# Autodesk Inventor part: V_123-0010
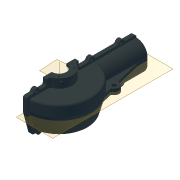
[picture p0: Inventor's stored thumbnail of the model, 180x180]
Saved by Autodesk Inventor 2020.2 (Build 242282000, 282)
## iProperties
Created: 2006-02
Part Number: V_123-0010
Document SubType Name: Modeling
Designer: F.Stasiak
Description: Obudowa - prawa
Material: L450
Project: Przekładnia X51
Mass: 3378.39 g
Surface Area: 1383.42 cm^2
Volume: 465.985 cm^3
Density: 7.25 g/cm^3
Appearance: Brąz armatni (nowy/polerowany)
Manager: www.cadconsulting.pl
Company: Fabian Stasiak CAD Consulting
Author: F.Stasiak
Subject: Zbiór ćwiczeń. Autodesk Inventor 2020. Kurs podstawowy
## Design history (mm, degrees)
sketch "Szkic1"
  geometry: L1 (0, -90)-(0, 90); A1 r 90 centre (0, 0) between (0, -90) and (0, 90); 2 further points
  constraints: 2 end point, 2 midpoint, 2 point on circle, 1 centre point, 1 coincident, 1 vertical, 1 other
  dimensions: "d0" = 90 radius of A1
extrude "Wyciągnięcie proste1" new body sketch "Szkic1" distance "d1" = 80; taper "d2" = 0 deg
node "Płaszczyzna konstrukcyjna4"
feature "Podział1"
feature "Szkic powierzchni2" dims angle "d38" = 15 deg
sketch "Szkic3"
  geometry: L1 (-78, 290)-(0, 290); L2 (0, 290)-(0, 150); L3 (0, 150)-(-78, 150); L4 (-78, 150)-(-78, 290); L5 (0, 0)-(0, 180) reference; L6 (34.5, 90)-(-126.5, 90) reference
  constraints: 10 end point, 2 horizontal, 2 parallel, 1 collinear, 1 perpendicular, 2 other
  dimensions: "d7" = 78 distance of L2.end L3.end; "d8" = 140 distance of L1.end L2.end; "d9" = 60 distance between parallel lines of L6 L3
extrude "Wyciągnięcie proste3" join sketch "Szkic3" distance "d10" = 40; taper "d11" = 0 deg
fillet "Zaokrąglenie1" dims "d12" = 30
node "Oś konstrukcyjna1"
feature "Skorupa1" dims "d13" = 5
sketch "Szkic4"
  geometry: L1 (2, 196.603)-(80, 196.603); L2 (80, 196.603)-(80, 156.603); L3 (80, 156.603)-(2, 156.603); L4 (2, 156.603)-(2, 196.603); L5 (80, -13.397)-(80, 276.603) reference; L6 (2, 153.741)-(2, 276.603) reference; L7 (2, 246.603)-(80, 246.603); L8 (80, 246.603)-(80, 276.603); L9 (80, 276.603)-(2, 276.603); L10 (2, 276.603)-(2, 246.603); L11 (2, 276.603)-(80, 276.603) reference
  constraints: 16 end point, 5 collinear, 4 parallel, 2 horizontal, 2 perpendicular
  dimensions: "d14" = 40 distance of L1.end L2.end; "d15" = 30 distance between parallel lines of L9 L7; "d16" = 50 distance between parallel lines of L1 L7
extrude "Wyciągnięcie proste4" join sketch "Szkic4" stored distance "d17" = 30; taper "d18" = 0 deg
node "Płaszczyzna konstrukcyjna1"
sketch "Szkic5"
  geometry: C1 r 27.5 at (0, -22.5) reference
extrude "Wyciągnięcie proste5" cut sketch "Szkic5" distance "d19" = 25; taper "d20" = 0 deg
node "Płaszczyzna konstrukcyjna2"
sketch "Szkic6"
  geometry: C1 r 23.5 at (0, -18) reference
extrude "Wyciągnięcie proste6" cut sketch "Szkic6" extent not by distance; stored distance "d21" = 12; taper "d22" = 0 deg
sketch "Szkic7"
  geometry: C1 r 18.1 at (0, 33.423) reference; C2 r 22.5 at (0, 33.423)
  constraints: 1 centre point, 1 coincident
  dimensions: "d23" = 45 diameter of C2
extrude "Wyciągnięcie proste7" cut sketch "Szkic7" stored distance "d24" = 12; taper "d25" = 0 deg
sketch "Szkic8"
  geometry: C1 r 23.5 at (0, 34.577) reference; C2 r 20 at (0, 34.577)
  constraints: 1 centre point, 1 coincident
  dimensions: "d26" = 40 diameter of C2
extrude "Wyciągnięcie proste8" cut sketch "Szkic8" extent not by distance; stored distance "d27" = 12; taper "d28" = 0 deg
sketch "Szkic9"
  geometry: L1 (80, 76.603)-(104, 76.603); L2 (104, 76.603)-(104, 40.603); L3 (104, 40.603)-(80, 40.603); L4 (80, 40.603)-(80, 76.603); L5 (104.002, 76.603)-(-8, 76.603) reference; L6 (80, -13.397)-(80, 276.603) reference
  constraints: 8 end point, 2 collinear, 2 parallel, 1 horizontal, 1 perpendicular
  dimensions: "d29" = 24 distance of L2.end L3.end; "d30" = 36 distance of L1.end L2.end
revolve "Obrót1" sketch "Szkic9" stored, may be unused: angle "d31" = 180 deg
node "Płaszczyzna konstrukcyjna3"
sketch "Szkic10"
  geometry: C1 r 23.5 at (0, -18) reference
extrude "Wyciągnięcie proste9" cut sketch "Szkic10" stored distance "d32" = 10; taper "d33" = 0 deg
sketch "Szkic12"
  geometry: C1 r 27.5 at (28.723, -80); A1 r 23.5 centre (28.723, -80) between (28.723, -56.5) and (28.723, -103.5) reference
  constraints: 1 centre point, 1 coincident
  dimensions: "d39" = 4 radial gap between concentric circles of A1 C1
extrude "Wyciągnięcie proste11" cut sketch "Szkic12" distance "d40" = 6; taper "d41" = 0 deg
sketch "Szkic13"
  geometry: L1 (0, 76.603)-(0, -76.603) reference; A1 r 36 centre (0, 0) between (0, 36) and (0, -36) reference
extrude "Wyciągnięcie proste12" join sketch "Szkic13" distance "d42" = 20; taper "d43" = 0 deg
node "Płaszczyzna konstrukcyjna5"
sketch "Szkic14"
  geometry: C1 r 23.5 at (0, -18) reference
extrude "Wyciągnięcie proste13" cut sketch "Szkic14" stored distance "d44" = 20; taper "d45" = 0 deg
sketch "Szkic16"
  geometry: C1 r 20 at (0, 18); A1 r 11 centre (0, 18) between (9.927, 22.739) and (7.275, 26.251) reference
  constraints: 1 centre point
  dimensions: "d49" = 40 diameter of C1
extrude "Wyciągnięcie proste15" cut sketch "Szkic16" extent not by distance; stored distance "d50" = 20; taper "d51" = 0 deg
sketch "Szkic17"
  geometry: C1 r 20 at (0, 18); A1 r 20 centre (0, 18) between (-1.231, -1.962) and (1.231, 37.962) reference
  constraints: 1 centre point, 1 coincident, 1 concentric
extrude "Wyciągnięcie proste16" cut sketch "Szkic17" extent not by distance; stored distance "d52" = 20; taper "d53" = 0 deg
sketch "Szkic18"
  geometry: L1 (-2, -113.138)-(-2, -153.741) reference; L2 (48, -167.138)-(-2, -153.741) reference; L3 (78, -167.138)-(48, -167.138) reference; L4 (78, -167.138)-(78, -113.138) reference; L5 (102, -113.138)-(78, -113.138) reference; L6 (-2, -113.138)-(-22, -113.138) reference; L7 (102, -121.138)-(86, -121.138); L8 (86, -121.138)-(86, -175.138); L9 (86, -175.138)-(46.947, -175.138); L10 (46.947, -175.138)-(-10, -159.88); L11 (-10, -159.88)-(-10, -121.138); L12 (-10, -121.138)-(-22, -121.138); L13 (102, -111.138)-(76, -111.138); L14 (76, -111.138)-(76, -165.138); L15 (76, -165.138)-(48.263, -165.138); L16 (48.263, -165.138)-(0, -152.206); L17 (0, -152.206)-(0, -111.138); L18 (0, -111.138)-(-22, -111.138); L19 (-22, -121.138)-(-22, -111.138); L20 (102, -121.138)-(102, -111.138)
  constraints: 28 end point, 1 parallel, 1 perpendicular, 10 other
  dimensions: "d54" = 8 distance between parallel lines of L6 L12; "d55" = 10 distance between parallel lines of L18 L12
extrude "Wyciągnięcie proste17" join sketch "Szkic18" distance "d56" = 10; taper "d57" = 0 deg
sketch "Szkic19"
  geometry: L1 (-2, -41.138)-(-22, -41.138) reference; L2 (-2, -0.536)-(-2, -41.138) reference; L3 (0, 0)-(0, 122.862) reference; L4 (78, -41.138)-(102, -41.138) reference; L5 (78, -41.138)-(78, 122.862) reference; L6 (-22, -33.138)-(-10, -33.138); L7 (-10, -33.138)-(-10, -0.536); L8 (-10, 0)-(-10, 122.862); L9 (102, -34.138)-(85, -34.138); L10 (85, -34.138)-(85, 122.862); L11 (-10, -0.536)-(-10, 0); L12 (0, -0.536)-(0, -43.138); L13 (0, -43.138)-(-22, -43.138); L14 (0, 0)-(0, 122.862); L15 (0, -0.536)-(0, 0); L16 (-22, -43.138)-(-22, -33.138); L17 (0, 122.862)-(-10, 122.862); L18 (102, -44.138)-(75, -44.138); L19 (75, -44.138)-(75, 122.862); L20 (102, -44.138)-(102, -34.138); L21 (75, 122.862)-(85, 122.862)
  constraints: 32 end point, 5 perpendicular, 3 collinear, 2 parallel, 4 other
  dimensions: "d58" = 8 distance between parallel lines of L6 L1; "d59" = 10 distance between parallel lines of L13 L6; "d60" = 7 distance between parallel lines of L9 L4; "d61" = 10 distance between parallel lines of L18 L9
extrude "Wyciągnięcie proste18" join sketch "Szkic19" distance "d62" = 10; taper "d63" = 0 deg
sketch "Szkic20"
  geometry: L1 (-58.658, 2.259)-(-58.658, 41) reference; L2 (-58.658, 129)-(-58.658, 285) reference; L3 (36.342, 128)-(36.342, 285) reference; L4 (37.342, 41)-(37.342, -13) reference; C1 r 8 at (-58.658, 21.629); C2 r 8 at (-58.658, 165); C3 r 8 at (-58.658, 245); C4 r 8 at (37.342, 14); C5 r 8 at (36.342, 164); C6 r 8 at (36.342, 244); 1 further point
  constraints: 6 centre point, 5 equal radius, 4 point on line, 2 midpoint, 1 coincident
  dimensions: "d64" = 16 diameter of C1; "d65" = 80 distance of C3.centre C2.centre; "d66" = 36 distance of C2.centre L2.start; "d67" = 80 distance of C6.centre C5.centre; "d68" = 36 distance of L3.start C5.centre
extrude "Wyciągnięcie proste19" join sketch "Szkic20" distance "d69" = 10; taper "d70" = 0 deg
fillet "Zaokrąglenie2" dims "d71" = 5
fillet "Zaokrąglenie3" dims "d72" = 5
fillet "Zaokrąglenie4" dims "d73" = 5
fillet "Zaokrąglenie5" dims "d74" = 5
sketch "Szkic21"
  geometry: A1 r 8 centre (-15, 40) between (-18.077, 47.385) and (-18.077, 32.615) reference; A2 r 8 centre (-15, -40) between (-18.077, -32.615) and (-18.077, -47.385) reference; A3 r 8 centre (-15, -183.371) between (-18.077, -175.986) and (-18.077, -190.755) reference; A4 r 8 centre (81, -191) between (84.077, -198.385) and (84.077, -183.615) reference; A5 r 8 centre (80, 39) between (83.077, 31.615) and (83.077, 46.385) reference; A6 r 8 centre (80, -41) between (83.077, -48.385) and (83.077, -33.615) reference
hole "Otwór1" sketch "Szkic21" at (-15, -183.371), (-15, -40), (-15, 40), (80, 39), (80, -41), (81, -191) diameter "d77" = 5.5; stored, may be unused: countersink angle "d81" = 90 deg, drill point angle "d83" = 118 deg; dims "d78" = 6, "d79" = 4, "d80" = 2, "d82" = 8
node "Płaszczyzna konstrukcyjna6"
sketch "Szkic22"
  geometry: L1 (-1.034, -22.661)-(29.062, -146.052)
  constraints: 2 end point
feature "Żebro1" sketch "Szkic22" dims "d84" = 1, "d85" = 15
sketch "Szkic23"
  geometry: L1 (-30.326, -26.891)-(0, 97.446) reference; C1 r 12.5 at (-20.269, 14.345); A1 r 20 centre (40, -75.655) between (40, -55.655) and (40, -95.655) reference
  constraints: 1 centre point, 1 point on line
  dimensions: "d87" = 25 diameter of C1; "d88" = 90 vertical distance of A1.centre C1.centre
extrude "Wyciągnięcie proste21" join sketch "Szkic23" stored distance "d92" = 10; taper "d93" = 0 deg
fillet "Zaokrąglenie8" dims "d94" = 5
sketch "Szkic24"
  geometry: A1 r 12.5 centre (-20.269, 14.345) between (-20.9, 26.829) and (-26.577, 3.553) reference
hole "Otwór2" sketch "Szkic24" at (-20.269, 14.345) diameter "d95" = 10; stored, may be unused: countersink angle "d99" = 90 deg, drill point angle "d101" = 118 deg; dims "d96" = 6, "d97" = 4, "d98" = 2, "d100" = 8
chamfer "Faza1" distance "d102" = 1; stored, may be unused: second distance "d103" = 2, angle "d104" = 45 deg
sketch "Szkic25"
  geometry: C1 r 2.75 at (-20.86, 20.86) reference; C2 r 2.75 at (-20.86, -20.86) reference
  constraints: 1 centre point, 2 other
hole "Otwór3" sketch "Szkic25" at (-20.86, 20.86), (-20.86, -20.86) diameter "d105" = 4.134; stored, may be unused: countersink angle "d109" = 90 deg, drill point angle "d111" = 118 deg; dims "d106" = 8, "d107" = 4, "d108" = 2, "d110" = 12
sketch "Szkic26"
  geometry: C1 r 2.75 at (20.86, -20.86) reference; C2 r 2.75 at (20.86, 20.86) reference
  constraints: 2 centre point, 4 other
hole "Otwór4" sketch "Szkic26" at (20.86, -20.86), (20.86, 20.86) diameter "d112" = 4.134; stored, may be unused: countersink angle "d116" = 90 deg, drill point angle "d118" = 118 deg; dims "d113" = 8, "d114" = 4, "d115" = 2, "d117" = 12
sketch "Szkic27"
  geometry: C1 r 3 at (-17.019, 31.404) reference; C2 r 3 at (-17.019, -14.558) reference
  constraints: 2 centre point, 4 other
hole "Otwór5" sketch "Szkic27" at (-17.019, 31.404), (-17.019, -14.558) diameter "d119" = 4.134; stored, may be unused: countersink angle "d123" = 90 deg, drill point angle "d125" = 118 deg; dims "d120" = 8, "d121" = 4, "d122" = 2, "d124" = 12
node "Bryła1"
node "Korpusy bryłowe"
node "Korpusy powierzchniowe"
node "Odniesienie1"
node "Odniesienie2"
node "Odniesienie3"
node "Odniesienie4"
node "Odniesienie5"
node "Odniesienie6"
node "Odniesienie8"
